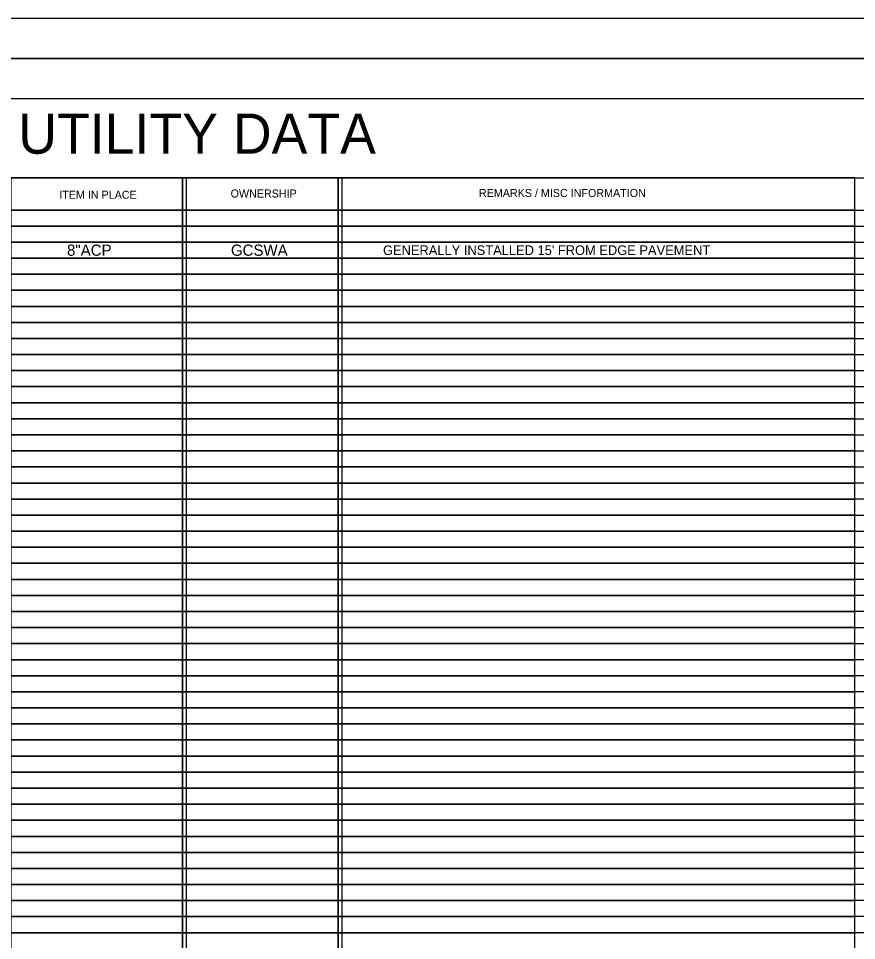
# Model space of a CAD drawing. Extents: x 11473 to 13269, y 16929 to 18079.
# Drawn here: x 11871 to 12394, y 17505 to 18079 of the extents above; entities that cross this region are included whole.
import ezdxf

# ---------------------------------------------------------------- set-up
doc = ezdxf.new("R2010")
doc.units = 0
for name, color, linetype in [('RD_SHT_Bndy', 7, 'Continuous'), ('RD_SHT_Iplotshp', 7, 'Continuous'), ('RD_SHT_Misc2', 7, 'Continuous'), ('RD_SHT_TX', 7, 'Continuous')]:
    doc.layers.add(name, color=color, linetype=linetype)

msp = doc.modelspace()

# ---------------------------------------------------------------- linework, layer by layer
at = {"layer": 'RD_SHT_Bndy'}
for p, q in [((13251.23, 18079.35), (11491.23, 18079.35)), ((13251.23, 18054.35), (11491.23, 18054.35)), ((13248.83, 18029.35), (11573.83, 18029.35))]:
    msp.add_line(p, q, dxfattribs=at)
for points in [[(11866.84, 17960), (11973.81, 17960), (11973.81, 17980.01), (11866.84, 17980.01)], [(11973.81, 17960), (12070.82, 17960), (12070.82, 17979.99), (11973.81, 17979.99)], [(12070.82, 17960), (12392.84, 17960), (12392.84, 17979.97), (12070.82, 17979.97)], [(11866.84, 17950), (11973.81, 17950), (11973.81, 17960), (11866.84, 17960)], [(11973.81, 17950), (12070.82, 17950), (12070.82, 17960), (11973.81, 17960)], [(12392.84, 17960), (12070.82, 17960), (12070.82, 17950), (12392.84, 17950)], [(11866.84, 17939.99), (11973.81, 17939.99), (11973.81, 17950), (11866.84, 17950)], [(11973.81, 17939.99), (12070.82, 17939.99), (12070.82, 17950), (11973.81, 17950)], [(12392.84, 17950), (12070.82, 17950), (12070.82, 17939.99), (12392.84, 17939.99)], [(11866.84, 17929.99), (11973.81, 17929.99), (11973.81, 17939.99), (11866.84, 17939.99)], [(11973.81, 17929.99), (12070.82, 17929.99), (12070.82, 17939.99), (11973.81, 17939.99)], [(12392.84, 17939.99), (12070.82, 17939.99), (12070.82, 17929.99), (12392.84, 17929.99)], [(11866.84, 17919.99), (11973.81, 17919.99), (11973.81, 17929.99), (11866.84, 17929.99)], [(11973.81, 17919.99), (12070.82, 17919.99), (12070.82, 17929.99), (11973.81, 17929.99)], [(12392.84, 17929.99), (12070.82, 17929.99), (12070.82, 17919.99), (12392.84, 17919.99)], [(11866.84, 17909.98), (11973.81, 17909.98), (11973.81, 17919.99), (11866.84, 17919.99)], [(11973.81, 17909.98), (12070.82, 17909.98), (12070.82, 17919.99), (11973.81, 17919.99)], [(12392.84, 17919.99), (12070.82, 17919.99), (12070.82, 17909.98), (12392.84, 17909.98)], [(11866.84, 17899.98), (11973.81, 17899.98), (11973.81, 17909.98), (11866.84, 17909.98)], [(11973.81, 17899.98), (12070.82, 17899.98), (12070.82, 17909.98), (11973.81, 17909.98)], [(12392.84, 17909.98), (12070.82, 17909.98), (12070.82, 17899.98), (12392.84, 17899.98)], [(11866.84, 17889.97), (11973.81, 17889.97), (11973.81, 17899.98), (11866.84, 17899.98)], [(11973.81, 17889.97), (12070.82, 17889.97), (12070.82, 17899.98), (11973.81, 17899.98)], [(12392.84, 17899.98), (12070.82, 17899.98), (12070.82, 17889.97), (12392.84, 17889.97)], [(11866.84, 17879.97), (11973.81, 17879.97), (11973.81, 17889.97), (11866.84, 17889.97)], [(11973.81, 17879.97), (12070.82, 17879.97), (12070.82, 17889.97), (11973.81, 17889.97)], [(12392.84, 17889.97), (12070.82, 17889.97), (12070.82, 17879.97), (12392.84, 17879.97)], [(11866.84, 17869.96), (11973.81, 17869.96), (11973.81, 17879.97), (11866.84, 17879.97)], [(11973.81, 17869.96), (12070.82, 17869.96), (12070.82, 17879.97), (11973.81, 17879.97)], [(12392.84, 17879.97), (12070.82, 17879.97), (12070.82, 17869.96), (12392.84, 17869.96)], [(11866.84, 17859.96), (11973.81, 17859.96), (11973.81, 17869.96), (11866.84, 17869.96)], [(11973.81, 17859.96), (12070.82, 17859.96), (12070.82, 17869.96), (11973.81, 17869.96)], [(12392.84, 17869.96), (12070.82, 17869.96), (12070.82, 17859.96), (12392.84, 17859.96)], [(11866.84, 17849.96), (11973.81, 17849.96), (11973.81, 17859.96), (11866.84, 17859.96)], [(11973.81, 17849.96), (12070.82, 17849.96), (12070.82, 17859.96), (11973.81, 17859.96)], [(12392.84, 17859.96), (12070.82, 17859.96), (12070.82, 17849.96), (12392.84, 17849.96)], [(11866.84, 17839.95), (11973.81, 17839.95), (11973.81, 17849.96), (11866.84, 17849.96)], [(11973.81, 17839.95), (12070.82, 17839.95), (12070.82, 17849.96), (11973.81, 17849.96)], [(12392.84, 17849.96), (12070.82, 17849.96), (12070.82, 17839.95), (12392.84, 17839.95)], [(11866.84, 17829.95), (11973.81, 17829.95), (11973.81, 17839.95), (11866.84, 17839.95)], [(11973.81, 17829.95), (12070.82, 17829.95), (12070.82, 17839.95), (11973.81, 17839.95)], [(12392.84, 17839.95), (12070.82, 17839.95), (12070.82, 17829.95), (12392.84, 17829.95)], [(11866.84, 17819.94), (11973.81, 17819.94), (11973.81, 17829.95), (11866.84, 17829.95)], [(11973.81, 17819.94), (12070.82, 17819.94), (12070.82, 17829.95), (11973.81, 17829.95)], [(12392.84, 17829.95), (12070.82, 17829.95), (12070.82, 17819.94), (12392.84, 17819.94)], [(11866.84, 17809.94), (11973.81, 17809.94), (11973.81, 17819.94), (11866.84, 17819.94)], [(11973.81, 17809.94), (12070.82, 17809.94), (12070.82, 17819.94), (11973.81, 17819.94)], [(12392.84, 17819.94), (12070.82, 17819.94), (12070.82, 17809.94), (12392.84, 17809.94)], [(11866.84, 17799.93), (11973.81, 17799.93), (11973.81, 17809.94), (11866.84, 17809.94)], [(11973.81, 17799.93), (12070.82, 17799.93), (12070.82, 17809.94), (11973.81, 17809.94)], [(12392.84, 17809.94), (12070.82, 17809.94), (12070.82, 17799.93), (12392.84, 17799.93)], [(11866.84, 17789.93), (11973.81, 17789.93), (11973.81, 17799.93), (11866.84, 17799.93)], [(11973.81, 17789.93), (12070.82, 17789.93), (12070.82, 17799.93), (11973.81, 17799.93)], [(12392.84, 17799.93), (12070.82, 17799.93), (12070.82, 17789.93), (12392.84, 17789.93)], [(11866.84, 17779.93), (11973.81, 17779.93), (11973.81, 17789.93), (11866.84, 17789.93)], [(11973.81, 17779.93), (12070.82, 17779.93), (12070.82, 17789.93), (11973.81, 17789.93)], [(12392.84, 17789.93), (12070.82, 17789.93), (12070.82, 17779.93), (12392.84, 17779.93)], [(11866.84, 17769.92), (11973.81, 17769.92), (11973.81, 17779.93), (11866.84, 17779.93)], [(11973.81, 17769.92), (12070.82, 17769.92), (12070.82, 17779.93), (11973.81, 17779.93)], [(12392.84, 17779.93), (12070.82, 17779.93), (12070.82, 17769.92), (12392.84, 17769.92)], [(11866.84, 17759.92), (11973.81, 17759.92), (11973.81, 17769.92), (11866.84, 17769.92)], [(11973.81, 17759.92), (12070.82, 17759.92), (12070.82, 17769.92), (11973.81, 17769.92)], [(12392.84, 17769.92), (12070.82, 17769.92), (12070.82, 17759.92), (12392.84, 17759.92)], [(11866.84, 17749.91), (11973.81, 17749.91), (11973.81, 17759.92), (11866.84, 17759.92)], [(11973.81, 17749.91), (12070.82, 17749.91), (12070.82, 17759.92), (11973.81, 17759.92)], [(12392.84, 17759.92), (12070.82, 17759.92), (12070.82, 17749.91), (12392.84, 17749.91)], [(11866.84, 17739.91), (11973.81, 17739.91), (11973.81, 17749.91), (11866.84, 17749.91)], [(11973.81, 17739.91), (12070.82, 17739.91), (12070.82, 17749.91), (11973.81, 17749.91)], [(12392.84, 17749.91), (12070.82, 17749.91), (12070.82, 17739.91), (12392.84, 17739.91)], [(11866.84, 17729.9), (11973.81, 17729.9), (11973.81, 17739.91), (11866.84, 17739.91)], [(11973.81, 17729.9), (12070.82, 17729.9), (12070.82, 17739.91), (11973.81, 17739.91)], [(12392.84, 17739.91), (12070.82, 17739.91), (12070.82, 17729.9), (12392.84, 17729.9)], [(11866.84, 17719.9), (11973.81, 17719.9), (11973.81, 17729.9), (11866.84, 17729.9)], [(11973.81, 17719.9), (12070.82, 17719.9), (12070.82, 17729.9), (11973.81, 17729.9)], [(12392.84, 17729.9), (12070.82, 17729.9), (12070.82, 17719.9), (12392.84, 17719.9)], [(11866.84, 17709.9), (11973.81, 17709.9), (11973.81, 17719.9), (11866.84, 17719.9)], [(11973.81, 17709.9), (12070.82, 17709.9), (12070.82, 17719.9), (11973.81, 17719.9)], [(12392.84, 17719.9), (12070.82, 17719.9), (12070.82, 17709.9), (12392.84, 17709.9)], [(11866.84, 17699.89), (11973.81, 17699.89), (11973.81, 17709.9), (11866.84, 17709.9)], [(11973.81, 17699.89), (12070.82, 17699.89), (12070.82, 17709.9), (11973.81, 17709.9)], [(12392.84, 17709.9), (12070.82, 17709.9), (12070.82, 17699.89), (12392.84, 17699.89)], [(11866.84, 17689.89), (11973.81, 17689.89), (11973.81, 17699.89), (11866.84, 17699.89)], [(11973.81, 17689.89), (12070.82, 17689.89), (12070.82, 17699.89), (11973.81, 17699.89)], [(12392.84, 17699.89), (12070.82, 17699.89), (12070.82, 17689.89), (12392.84, 17689.89)], [(11866.84, 17679.88), (11973.81, 17679.88), (11973.81, 17689.89), (11866.84, 17689.89)], [(11973.81, 17679.88), (12070.82, 17679.88), (12070.82, 17689.89), (11973.81, 17689.89)], [(12392.84, 17689.89), (12070.82, 17689.89), (12070.82, 17679.88), (12392.84, 17679.88)], [(11866.84, 17669.88), (11973.81, 17669.88), (11973.81, 17679.88), (11866.84, 17679.88)], [(11973.81, 17669.88), (12070.82, 17669.88), (12070.82, 17679.88), (11973.81, 17679.88)], [(12392.84, 17679.88), (12070.82, 17679.88), (12070.82, 17669.88), (12392.84, 17669.88)], [(11866.84, 17659.87), (11973.81, 17659.87), (11973.81, 17669.88), (11866.84, 17669.88)], [(11973.81, 17659.87), (12070.82, 17659.87), (12070.82, 17669.88), (11973.81, 17669.88)], [(12392.84, 17669.88), (12070.82, 17669.88), (12070.82, 17659.87), (12392.84, 17659.87)], [(11866.84, 17649.87), (11973.81, 17649.87), (11973.81, 17659.87), (11866.84, 17659.87)], [(11973.81, 17649.87), (12070.82, 17649.87), (12070.82, 17659.87), (11973.81, 17659.87)], [(12392.84, 17659.87), (12070.82, 17659.87), (12070.82, 17649.87), (12392.84, 17649.87)], [(11866.84, 17639.87), (11973.81, 17639.87), (11973.81, 17649.87), (11866.84, 17649.87)], [(11973.81, 17639.87), (12070.82, 17639.87), (12070.82, 17649.87), (11973.81, 17649.87)], [(12392.84, 17649.87), (12070.82, 17649.87), (12070.82, 17639.87), (12392.84, 17639.87)], [(11866.84, 17629.86), (11973.81, 17629.86), (11973.81, 17639.87), (11866.84, 17639.87)], [(11973.81, 17629.86), (12070.82, 17629.86), (12070.82, 17639.87), (11973.81, 17639.87)], [(12392.84, 17639.87), (12070.82, 17639.87), (12070.82, 17629.86), (12392.84, 17629.86)], [(11866.84, 17619.86), (11973.81, 17619.86), (11973.81, 17629.86), (11866.84, 17629.86)], [(11973.81, 17619.86), (12070.82, 17619.86), (12070.82, 17629.86), (11973.81, 17629.86)], [(12392.84, 17629.86), (12070.82, 17629.86), (12070.82, 17619.86), (12392.84, 17619.86)], [(11866.84, 17609.85), (11973.81, 17609.85), (11973.81, 17619.86), (11866.84, 17619.86)], [(11973.81, 17609.85), (12070.82, 17609.85), (12070.82, 17619.86), (11973.81, 17619.86)], [(12392.84, 17619.86), (12070.82, 17619.86), (12070.82, 17609.85), (12392.84, 17609.85)], [(11866.84, 17599.85), (11973.81, 17599.85), (11973.81, 17609.85), (11866.84, 17609.85)], [(11973.81, 17599.85), (12070.82, 17599.85), (12070.82, 17609.85), (11973.81, 17609.85)], [(12392.84, 17609.85), (12070.82, 17609.85), (12070.82, 17599.85), (12392.84, 17599.85)], [(11866.84, 17589.84), (11973.81, 17589.84), (11973.81, 17599.85), (11866.84, 17599.85)], [(11973.81, 17589.84), (12070.82, 17589.84), (12070.82, 17599.85), (11973.81, 17599.85)], [(12392.84, 17599.85), (12070.82, 17599.85), (12070.82, 17589.84), (12392.84, 17589.84)], [(11866.84, 17579.84), (11973.81, 17579.84), (11973.81, 17589.84), (11866.84, 17589.84)], [(11973.81, 17579.84), (12070.82, 17579.84), (12070.82, 17589.84), (11973.81, 17589.84)], [(12392.84, 17589.84), (12070.82, 17589.84), (12070.82, 17579.84), (12392.84, 17579.84)], [(11866.84, 17569.83), (11973.81, 17569.83), (11973.81, 17579.84), (11866.84, 17579.84)], [(11973.81, 17569.83), (12070.82, 17569.83), (12070.82, 17579.84), (11973.81, 17579.84)], [(12392.84, 17579.84), (12070.82, 17579.84), (12070.82, 17569.83), (12392.84, 17569.83)], [(11866.84, 17559.83), (11973.81, 17559.83), (11973.81, 17569.83), (11866.84, 17569.83)], [(11973.81, 17559.83), (12070.82, 17559.83), (12070.82, 17569.83), (11973.81, 17569.83)], [(12392.84, 17569.83), (12070.82, 17569.83), (12070.82, 17559.83), (12392.84, 17559.83)], [(11866.84, 17549.83), (11973.81, 17549.83), (11973.81, 17559.83), (11866.84, 17559.83)], [(11973.81, 17549.83), (12070.82, 17549.83), (12070.82, 17559.83), (11973.81, 17559.83)], [(12392.84, 17559.83), (12070.82, 17559.83), (12070.82, 17549.83), (12392.84, 17549.83)], [(11866.84, 17539.82), (11973.81, 17539.82), (11973.81, 17549.83), (11866.84, 17549.83)], [(11973.81, 17539.82), (12070.82, 17539.82), (12070.82, 17549.83), (11973.81, 17549.83)], [(12392.84, 17549.83), (12070.82, 17549.83), (12070.82, 17539.82), (12392.84, 17539.82)], [(11866.84, 17529.82), (11973.81, 17529.82), (11973.81, 17539.82), (11866.84, 17539.82)], [(11973.81, 17529.82), (12070.82, 17529.82), (12070.82, 17539.82), (11973.81, 17539.82)], [(12392.84, 17539.82), (12070.82, 17539.82), (12070.82, 17529.82), (12392.84, 17529.82)], [(11866.84, 17519.81), (11973.81, 17519.81), (11973.81, 17529.82), (11866.84, 17529.82)], [(11973.81, 17519.81), (12070.82, 17519.81), (12070.82, 17529.82), (11973.81, 17529.82)], [(12392.84, 17529.82), (12070.82, 17529.82), (12070.82, 17519.81), (12392.84, 17519.81)], [(11866.84, 17509.81), (11973.81, 17509.81), (11973.81, 17519.81), (11866.84, 17519.81)], [(11973.81, 17509.81), (12070.82, 17509.81), (12070.82, 17519.81), (11973.81, 17519.81)], [(12392.84, 17519.81), (12070.82, 17519.81), (12070.82, 17509.81), (12392.84, 17509.81)], [(11866.84, 17499.8), (11973.81, 17499.8), (11973.81, 17509.81), (11866.84, 17509.81)], [(11973.81, 17499.8), (12070.82, 17499.8), (12070.82, 17509.81), (11973.81, 17509.81)], [(12392.84, 17509.81), (12070.82, 17509.81), (12070.82, 17499.8), (12392.84, 17499.8)]]:
    msp.add_lwpolyline(points, close=True, dxfattribs=at)
at = {"layer": 'RD_SHT_Iplotshp'}
msp.add_lwpolyline([(11472.63, 18054.35), (13268.63, 18054.35), (13268.63, 16954.35), (11472.63, 16954.35)], close=True, dxfattribs=at)
at = {"layer": 'RD_SHT_Misc2'}
for p, q in [((11576, 17979.97), (13244, 17979.97)), ((11975.97, 17980.01), (11975.97, 17110)), ((12072.98, 17979.99), (12072.98, 17110)), ((11576, 17960), (13244, 17960)), ((11576, 17950), (13244, 17950)), ((11576, 17940), (13244, 17940)), ((11576, 17930), (13244, 17930)), ((11576, 17920), (13244, 17920)), ((11576, 17910), (13244, 17910)), ((11576, 17900), (13244, 17900)), ((11576, 17890), (13244, 17890)), ((11576, 17880), (13244, 17880)), ((11576, 17870), (13244, 17870)), ((11576, 17860), (13244, 17860)), ((11576, 17850), (13244, 17850)), ((11576, 17840), (13244, 17840)), ((11576, 17830), (13244, 17830)), ((11576, 17820), (13244, 17820)), ((11576, 17810), (13244, 17810)), ((11576, 17800), (13244, 17800)), ((11576, 17790), (13244, 17790)), ((11576, 17780), (13244, 17780)), ((11576, 17770), (13244, 17770)), ((11576, 17760), (13244, 17760)), ((11576, 17750), (13244, 17750)), ((11576, 17740), (13244, 17740)), ((11576, 17730), (13244, 17730)), ((11576, 17720), (13244, 17720)), ((11576, 17710), (13244, 17710)), ((11576, 17700), (13244, 17700)), ((11576, 17690), (13244, 17690)), ((11576, 17680), (13244, 17680)), ((11576, 17670), (13244, 17670)), ((11576, 17660), (13244, 17660)), ((11576, 17650), (13244, 17650)), ((11576, 17640), (13244, 17640)), ((11576, 17630), (13244, 17630)), ((11576, 17620), (13244, 17620)), ((11576, 17610), (13244, 17610)), ((11576, 17600), (13244, 17600)), ((11576, 17590), (13244, 17590)), ((11576, 17580), (13244, 17580)), ((11576, 17570), (13244, 17570)), ((11576, 17560), (13244, 17560)), ((11576, 17550), (13244, 17550)), ((11576, 17540), (13244, 17540)), ((11576, 17530), (13244, 17530)), ((11576, 17520), (13244, 17520)), ((11576, 17510), (13244, 17510))]:
    msp.add_line(p, q, dxfattribs=at)

# ---------------------------------------------------------------- texts
at = {"layer": 'RD_SHT_TX'}
for s, height, p in [('UTILITY DATA', 25, (11871.41, 17995.1)), ('ITEM IN PLACE', 5, (11896.94, 17967.03)), ('OWNERSHIP', 5, (12003.76, 17967.79)), ('REMARKS / MISC INFORMATION', 5, (12158.54, 17968.11)), ('8"ACP', 7, (11901.78, 17931.49)), ('GCSWA', 7, (12003.96, 17931.49)), ("GENERALLY INSTALLED 15' FROM EDGE PAVEMENT", 6, (12098.74, 17931.99))]:
    msp.add_text(s, height=height, dxfattribs=at).set_placement(p)

doc.saveas('drawing.dxf')
